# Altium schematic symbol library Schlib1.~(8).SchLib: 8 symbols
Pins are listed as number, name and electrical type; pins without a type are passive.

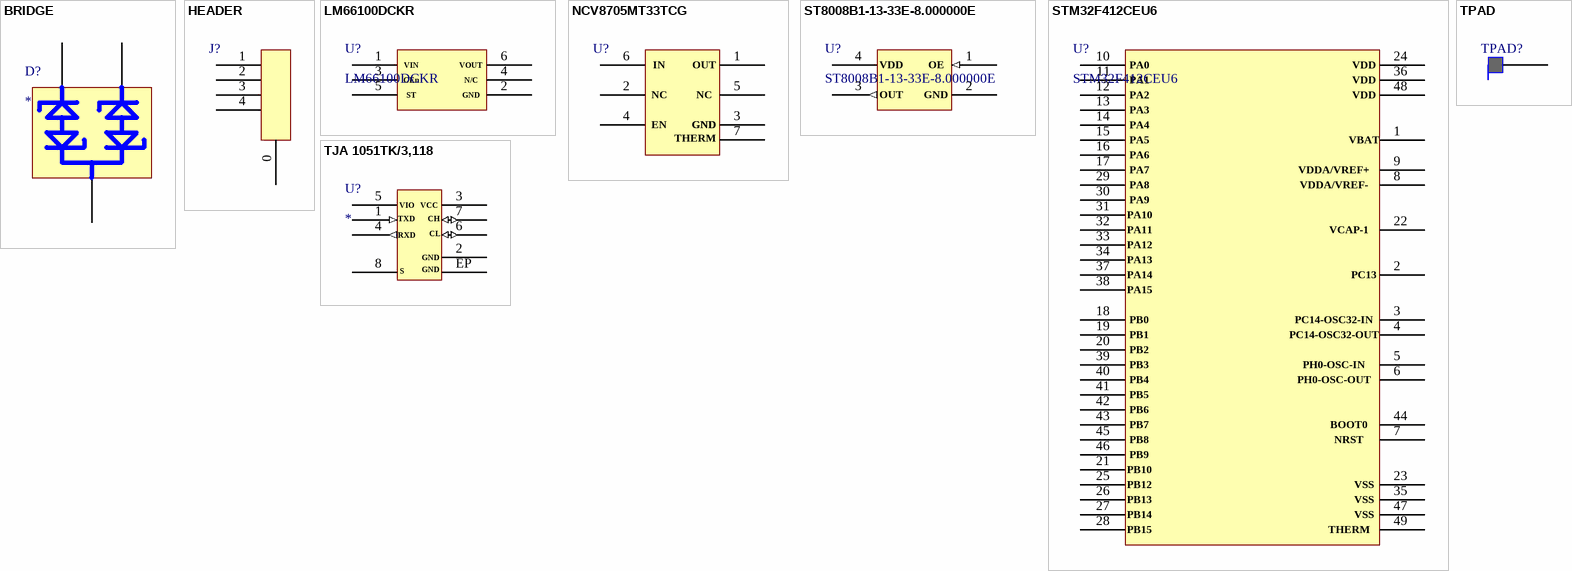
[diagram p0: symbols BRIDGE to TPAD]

## BRIDGE
designator D?
pins: 1, 2, 3

## HEADER
designator J?  (value not drawn)
pins: 0, 1, 2, 3, 4

## LM66100DCKR
designator U?
pins: 1, 2, 3, 4, 5, 6

## NCV8705MT33TCG
designator U?  (value not drawn)
pins: 1, 2, 3, 4, 5, 6, 7

## ST8008B1-13-33E-8.000000E
designator U?
pins: 1 (in), 2, 3 (out), 4 50

## STM32F412CEU6
designator U?
pins: 1, 2, 3, 4, 5, 6, 7, 8, 9, 10, 11, 12, 13, 14, 15, 16, 17, 18, 19, 20, 21, 22, 23, 24, 25, 26, 27, 28, 29, 30, 31, 32, 33, 34, 35, 36, 37, 38, 39, 40, 41, 42, 43, 44, 45, 46, 47, 48, 49

## TJA 1051TK/3,118
designator U?
pins: 1 (in), 2, 3, 4 (out), 5, 6 (io), 7 (io), 8, EP

## TPAD
designator TPAD?  (value not drawn)
pins: 1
